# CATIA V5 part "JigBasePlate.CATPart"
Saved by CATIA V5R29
Part number: JigBasePlate
Bounding box of the stored display mesh (mm): x -110 to 110, y -60 to 60, z 0 to 10
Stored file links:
  C:\Users\Administrator\Desktop\프로젝트\Boxfold\JigBasePlate.CATPart
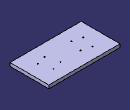
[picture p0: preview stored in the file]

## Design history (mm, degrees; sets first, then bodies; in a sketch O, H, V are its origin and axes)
Body1 (main body)
  DatumCurve1
  Sketch1 on xy-plane, origin (0, 0, 0), H (1, 0, 0), V (0, 1, 0)
    line L1 (-110, 60) -> (110, 60)
    line L2 (110, 60) -> (110, -60)
    line L3 (110, -60) -> (-110, -60)
    line L4 (-110, -60) -> (-110, 60)
    length L1 = 220
    distance L3 L1 = 120
    horizontal: L1 H, L3 H
    vertical: L2 V, L4 V
    symmetry: L2 L4 V, L1 L3 H
  Pad1: profile Sketch1, direction (0, 0, 1), length 10
  Sketch2 on end face of Pad1, origin (60.259, 24.5667, 10), H (1, 0, 0), V (0, 1, 0)
    point P1 (-0.2077, 0.226)
    reference projected circle E1 centre (-0.2077, 0.226) radius 2.25 from edge of DatumCurve1
    concentricity: E1 P1
  Hole1: placed by Sketch2, at (60.0513, 24.7926, 10) direction (0, 0, -1), diameter 3.242, depth 10, V-bottom angle 120, threaded "M4", thread diameter 4, thread depth 10, pitch 0.7
  DatumCurve2 to DatumCurve8
  Sketch3 on end face of Pad1, origin (0, 0, 10), H (-1, 0, 0), V (0, -1, 0)
    point P1 (-31.0735, -17.028)
    reference projected circle E1 centre (-31.0735, -17.028) radius 2.25 from edge of DatumCurve2
    point P2 (-41.4263, 21.609)
    point P3 (-70.4041, 13.8444)
    point P4 (41.4263, 21.609)
    point P5 (70.4041, 13.8444)
    point P6 (60.0513, -24.7926)
    point P7 (31.0735, -17.028)
    reference projected circle E2 centre (-41.4263, 21.609) radius 2.25 from edge of DatumCurve3
    reference projected circle E3 centre (-70.4041, 13.8444) radius 2.25 from edge of DatumCurve4
    reference projected circle E4 centre (41.4263, 21.609) radius 2.25 from edge of DatumCurve5
    reference projected circle E5 centre (70.4041, 13.8444) radius 2.25 from edge of DatumCurve6
    reference projected circle E6 centre (60.0513, -24.7926) radius 2.25 from edge of DatumCurve7
    reference projected circle E7 centre (31.0735, -17.028) radius 2.25 from edge of DatumCurve8
    concentricity: P1 E1, P2 E2, P3 E3, P4 E4, P5 E5, P6 E6, P7 E7
  UserPattern1: of Hole1, copies 8, at the points of Sketch3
